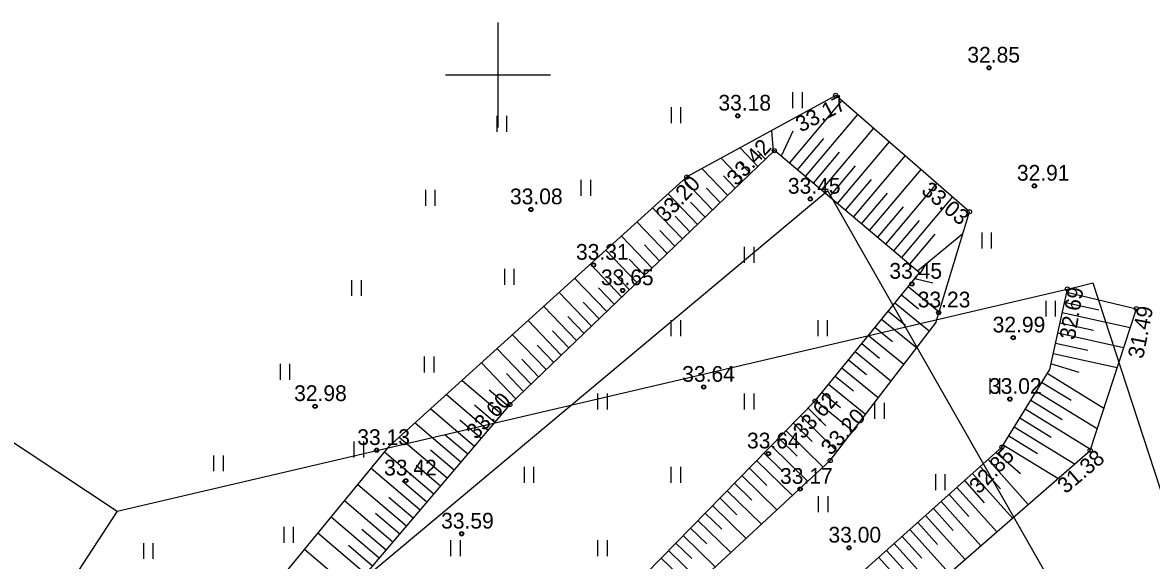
# Model space of a CAD drawing. Extents: x 641898 to 642452, y 6471715 to 6472255.
# Drawn here: x 642027.3 to 642081.1, y 6472226.8 to 6472252.5 of the extents above; entities that cross this region are included whole.
import ezdxf

# ---------------------------------------------------------------- set-up
doc = ezdxf.new("R2010")
doc.units = 0
for name, color, linetype in [('HALJASTUS', 7, 'Continuous'), ('KORGUS-EH2000', 7, 'Continuous'), ('MOOTMPUNKT', 7, 'Continuous'), ('MOOTPIIR', 7, 'Continuous'), ('PIIR', 7, 'Continuous'), ('RELJEEF', 7, 'Continuous'), ('VEEKOGU', 7, 'Continuous'), ('VORK', 7, 'Continuous')]:
    doc.layers.add(name, color=color, linetype=linetype)

msp = doc.modelspace()

# ---------------------------------------------------------------- linework, layer by layer
at = {"layer": 'HALJASTUS'}
for p, q in [((642064.043, 6472249.181), (642064.043, 6472248.42)), ((642064.498, 6472249.181), (642064.498, 6472248.42)), ((642058.249, 6472248.464), (642058.249, 6472247.703)), ((642058.704, 6472248.464), (642058.704, 6472247.703)), ((642049.945, 6472248.046), (642049.945, 6472247.285)), ((642050.4, 6472248.046), (642050.4, 6472247.285)), ((642053.948, 6472244.999), (642053.948, 6472244.238)), ((642054.403, 6472244.999), (642054.403, 6472244.238)), ((642046.54, 6472244.521), (642046.54, 6472243.76)), ((642046.995, 6472244.521), (642046.995, 6472243.76)), ((642073.063, 6472242.49), (642073.063, 6472241.729)), ((642073.518, 6472242.49), (642073.518, 6472241.729)), ((642061.743, 6472241.804), (642061.743, 6472241.043)), ((642062.198, 6472241.804), (642062.198, 6472241.043)), ((642050.304, 6472240.758), (642050.304, 6472239.997)), ((642050.759, 6472240.758), (642050.759, 6472239.997)), ((642043.016, 6472240.22), (642043.016, 6472239.459)), ((642043.471, 6472240.22), (642043.471, 6472239.459)), ((642076.11, 6472239.234), (642076.11, 6472238.473)), ((642076.565, 6472239.234), (642076.565, 6472238.473)), ((642058.243, 6472238.304), (642058.243, 6472237.543)), ((642058.698, 6472238.304), (642058.698, 6472237.543)), ((642065.243, 6472238.304), (642065.243, 6472237.543)), ((642065.698, 6472238.304), (642065.698, 6472237.543)), ((642046.48, 6472236.576), (642046.48, 6472235.815)), ((642046.935, 6472236.576), (642046.935, 6472235.815)), ((642039.611, 6472236.218), (642039.611, 6472235.457)), ((642040.066, 6472236.218), (642040.066, 6472235.457)), ((642073.452, 6472235.531), (642073.452, 6472234.77)), ((642073.907, 6472235.531), (642073.907, 6472234.77)), ((642054.743, 6472234.804), (642054.743, 6472234.043)), ((642055.198, 6472234.804), (642055.198, 6472234.043)), ((642061.743, 6472234.804), (642061.743, 6472234.043)), ((642062.198, 6472234.804), (642062.198, 6472234.043)), ((642067.956, 6472234.366), (642067.956, 6472233.605)), ((642068.411, 6472234.366), (642068.411, 6472233.605)), ((642043.135, 6472232.514), (642043.135, 6472231.753)), ((642043.59, 6472232.514), (642043.59, 6472231.753)), ((642036.445, 6472231.857), (642036.445, 6472231.096)), ((642036.9, 6472231.857), (642036.9, 6472231.096)), ((642051.243, 6472231.304), (642051.243, 6472230.543)), ((642051.698, 6472231.304), (642051.698, 6472230.543)), ((642058.243, 6472231.304), (642058.243, 6472230.543)), ((642058.698, 6472231.304), (642058.698, 6472230.543)), ((642070.853, 6472230.961), (642070.853, 6472230.2)), ((642071.308, 6472230.961), (642071.308, 6472230.2)), ((642065.268, 6472229.915), (642065.268, 6472229.154)), ((642065.723, 6472229.915), (642065.723, 6472229.154)), ((642039.79, 6472228.452), (642039.79, 6472227.691)), ((642040.245, 6472228.452), (642040.245, 6472227.691)), ((642033.099, 6472227.675), (642033.099, 6472226.914)), ((642033.554, 6472227.675), (642033.554, 6472226.914)), ((642047.743, 6472227.804), (642047.743, 6472227.043)), ((642048.198, 6472227.804), (642048.198, 6472227.043)), ((642054.743, 6472227.804), (642054.743, 6472227.043)), ((642055.198, 6472227.804), (642055.198, 6472227.043))]:
    msp.add_line(p, q, dxfattribs=at)
at = {"layer": 'KORGUS-EH2000'}
for centre in [(642073.407, 6472250.341), (642066.098, 6472249.025), (642061.431, 6472248.051), (642063.176, 6472246.392), (642059.006, 6472245.135), (642075.572, 6472244.709), (642064.89, 6472244.088), (642051.57, 6472243.583), (642072.479, 6472243.479), (642054.557, 6472240.937), (642069.73, 6472240.032), (642055.942, 6472239.723), (642077.147, 6472239.79), (642080.432, 6472238.853), (642071.008, 6472238.664), (642074.56, 6472237.469), (642059.803, 6472235.116), (642041.282, 6472234.197), (642050.565, 6472234.28), (642065.121, 6472234.45), (642074.403, 6472234.541), (642044.217, 6472232.101), (642062.892, 6472231.938), (642074.024, 6472232.25), (642078.23, 6472232.093), (642065.837, 6472231.608), (642045.608, 6472230.648), (642064.405, 6472230.25), (642048.27, 6472228.114), (642066.735, 6472227.445)]:
    msp.add_circle(centre, 0.1, dxfattribs=at)
at = {"layer": 'MOOTMPUNKT'}
for centre in [(642073.407, 6472250.341), (642061.431, 6472248.051), (642075.572, 6472244.709), (642064.89, 6472244.088), (642051.57, 6472243.583), (642054.557, 6472240.937), (642069.73, 6472240.032), (642055.942, 6472239.723), (642071.008, 6472238.664), (642074.56, 6472237.469), (642059.803, 6472235.116), (642041.282, 6472234.197), (642074.403, 6472234.541), (642044.217, 6472232.101), (642062.892, 6472231.938), (642045.608, 6472230.648), (642064.405, 6472230.25), (642048.27, 6472228.114), (642066.735, 6472227.445)]:
    msp.add_circle(centre, 0.075, dxfattribs=at)
at = {"layer": 'MOOTPIIR'}
msp.add_lwpolyline([(642014.306, 6472085.384), (642027.67, 6472104.979), (642055.501, 6472084.843), (642081.563, 6472094.262), (642123.938, 6472142.273), (642065.721, 6472244.475), (642008.922, 6472196.948), (642003.347, 6472200.453), (641979.65, 6472162.756), (641979.65, 6472162.756), (641986.045, 6472158.736), (642004.269, 6472142.365), (641987.048, 6472123.488), (641970.482, 6472097.889), (641986.758, 6472084.396)], close=True, dxfattribs=at)
at = {"layer": 'PIIR'}
for p, q in [((642077.68, 6472239.91), (642078.35, 6472240.08)), ((642078.35, 6472240.08), (642090.34, 6472203.36)), ((642031.85, 6472229.19), (642077.68, 6472239.91)), ((642022.295, 6472235.519), (642031.85, 6472229.19)), ((642031.85, 6472229.19), (642000.12, 6472180.55))]:
    msp.add_line(p, q, dxfattribs=at)
at = {"layer": 'RELJEEF'}
for p, q in [((642066.384, 6472248.776), (642063.878, 6472245.801)), ((642067.139, 6472248.12), (642064.642, 6472245.157)), ((642063.037, 6472247.346), (642063.116, 6472246.335)), ((642064.054, 6472247.327), (642063.495, 6472246.123)), ((642067.894, 6472247.464), (642065.407, 6472244.512)), ((642061.545, 6472246.528), (642062.395, 6472245.642)), ((642065.511, 6472246.963), (642064.26, 6472245.479)), ((642068.649, 6472246.808), (642066.172, 6472243.868)), ((642060.637, 6472246.029), (642061.674, 6472244.949)), ((642062.377, 6472246.383), (642062.756, 6472245.988)), ((642066.271, 6472246.313), (642065.025, 6472244.834)), ((642069.404, 6472246.152), (642066.937, 6472243.224)), ((642059.729, 6472245.531), (642060.953, 6472244.257)), ((642061.563, 6472245.787), (642062.035, 6472245.296)), ((642067.03, 6472245.663), (642065.79, 6472244.19)), ((642070.159, 6472245.496), (642067.701, 6472242.579)), ((642058.854, 6472244.998), (642060.232, 6472243.564)), ((642060.748, 6472245.192), (642061.313, 6472244.603)), ((642067.79, 6472245.013), (642066.554, 6472243.546)), ((642059.933, 6472244.596), (642060.592, 6472243.91)), ((642068.55, 6472244.363), (642067.319, 6472242.901)), ((642070.913, 6472244.84), (642068.466, 6472241.935)), ((642058.113, 6472244.326), (642059.51, 6472242.871)), ((642059.177, 6472243.94), (642059.871, 6472243.218)), ((642071.668, 6472244.184), (642069.231, 6472241.291)), ((642057.371, 6472243.655), (642058.789, 6472242.179)), ((642058.446, 6472243.258), (642059.15, 6472242.525)), ((642069.31, 6472243.712), (642068.084, 6472242.257)), ((642056.629, 6472242.984), (642058.068, 6472241.486)), ((642070.07, 6472243.062), (642068.849, 6472241.613)), ((642055.888, 6472242.312), (642057.347, 6472240.793)), ((642057.714, 6472242.576), (642058.428, 6472241.832)), ((642070.83, 6472242.412), (642069.613, 6472240.969)), ((642072.159, 6472242.426), (642069.996, 6472240.646)), ((642055.146, 6472241.641), (642056.625, 6472240.101)), ((642056.983, 6472241.894), (642057.707, 6472241.14)), ((642056.251, 6472241.212), (642056.986, 6472240.447)), ((642054.404, 6472240.969), (642055.904, 6472239.408)), ((642053.663, 6472240.298), (642055.183, 6472238.715)), ((642055.52, 6472240.53), (642056.265, 6472239.754)), ((642070.722, 6472240.069), (642069.865, 6472240.276)), ((642052.921, 6472239.627), (642054.462, 6472238.022)), ((642054.788, 6472239.848), (642055.544, 6472239.062)), ((642070.049, 6472238.837), (642069.234, 6472239.501)), ((642071.024, 6472238.688), (642069.549, 6472239.888)), ((642077.113, 6472239.634), (642080.432, 6472238.853)), ((642052.179, 6472238.955), (642053.74, 6472237.33)), ((642054.057, 6472239.166), (642054.822, 6472238.369)), ((642070.56, 6472237.776), (642068.918, 6472239.113)), ((642078.648, 6472238.783), (642077.005, 6472239.145)), ((642053.326, 6472238.484), (642054.101, 6472237.676)), ((642069.429, 6472238.052), (642068.602, 6472238.725)), ((642080.135, 6472237.943), (642076.897, 6472238.657)), ((642051.438, 6472238.284), (642053.019, 6472236.637)), ((642068.809, 6472237.267), (642067.971, 6472237.95)), ((642069.952, 6472236.982), (642068.286, 6472238.337)), ((642078.385, 6472237.817), (642076.789, 6472238.169)), ((642050.696, 6472237.613), (642052.298, 6472235.944)), ((642052.594, 6472237.802), (642053.38, 6472236.983)), ((642069.343, 6472236.187), (642067.655, 6472237.562)), ((642079.824, 6472236.987), (642076.682, 6472237.681)), ((642049.954, 6472236.941), (642051.577, 6472235.252)), ((642051.863, 6472237.119), (642052.659, 6472236.291)), ((642068.189, 6472236.482), (642067.339, 6472237.174)), ((642078.121, 6472236.851), (642076.574, 6472237.192)), ((642049.212, 6472236.27), (642050.856, 6472234.559)), ((642051.131, 6472236.437), (642051.937, 6472235.598)), ((642067.569, 6472235.697), (642066.708, 6472236.399)), ((642068.735, 6472235.393), (642067.024, 6472236.787)), ((642079.513, 6472236.032), (642076.466, 6472236.704)), ((642050.4, 6472235.755), (642051.216, 6472234.905)), ((642068.127, 6472234.599), (642066.392, 6472236.011)), ((642078.882, 6472234.096), (642076.179, 6472235.757)), ((642077.711, 6472235.807), (642076.358, 6472236.216)), ((642048.289, 6472235.434), (642050.178, 6472233.825)), ((642067.519, 6472233.804), (642065.761, 6472235.236)), ((642066.95, 6472234.912), (642066.076, 6472235.623)), ((642077.32, 6472234.469), (642075.917, 6472235.331)), ((642047.541, 6472234.757), (642049.53, 6472233.064)), ((642049.582, 6472234.989), (642050.502, 6472234.206)), ((642066.33, 6472234.127), (642065.445, 6472234.848)), ((642078.564, 6472233.118), (642075.655, 6472234.905)), ((642048.884, 6472234.27), (642049.854, 6472233.445)), ((642066.91, 6472233.01), (642065.129, 6472234.46)), ((642076.899, 6472233.554), (642075.393, 6472234.479)), ((642046.793, 6472234.08), (642048.881, 6472232.302)), ((642066.17, 6472232.043), (642064.431, 6472233.745)), ((642065.628, 6472233.272), (642064.78, 6472234.102)), ((642076.371, 6472232.704), (642074.87, 6472233.627)), ((642078.245, 6472232.14), (642075.132, 6472234.053)), ((642046.046, 6472233.403), (642048.233, 6472231.541)), ((642048.186, 6472233.551), (642049.206, 6472232.683)), ((642065.502, 6472231.297), (642063.731, 6472233.03)), ((642064.972, 6472232.515), (642064.081, 6472233.387)), ((642077.478, 6472231.437), (642074.608, 6472233.201)), ((642045.298, 6472232.726), (642047.585, 6472230.779)), ((642047.488, 6472232.832), (642048.557, 6472231.922)), ((642064.258, 6472231.815), (642063.382, 6472232.673)), ((642075.715, 6472231.934), (642074.346, 6472232.775)), ((642044.586, 6472232.019), (642046.937, 6472230.018)), ((642046.79, 6472232.112), (642047.909, 6472231.16)), ((642063.541, 6472231.118), (642062.682, 6472231.958)), ((642064.767, 6472230.617), (642063.032, 6472232.315)), ((642074.904, 6472230.969), (642073.738, 6472231.994)), ((642076.689, 6472230.748), (642074.085, 6472232.349)), ((642064.032, 6472229.937), (642062.332, 6472231.601)), ((642075.281, 6472229.52), (642073.365, 6472231.66)), ((642043.951, 6472231.246), (642046.289, 6472229.257)), ((642046.093, 6472231.393), (642047.261, 6472230.399)), ((642063.297, 6472229.257), (642061.633, 6472230.886)), ((642062.824, 6472230.42), (642061.983, 6472231.243)), ((642074.528, 6472228.862), (642072.62, 6472230.993)), ((642073.948, 6472230.259), (642072.993, 6472231.327)), ((642043.317, 6472230.473), (642045.64, 6472228.495)), ((642045.441, 6472230.635), (642046.613, 6472229.637)), ((642062.107, 6472229.723), (642061.283, 6472230.529)), ((642073.199, 6472229.597), (642072.247, 6472230.66)), ((642044.799, 6472229.868), (642045.964, 6472228.876)), ((642061.39, 6472229.025), (642060.584, 6472229.814)), ((642062.563, 6472228.577), (642060.933, 6472230.171)), ((642072.45, 6472228.934), (642071.502, 6472229.993)), ((642073.774, 6472228.205), (642071.875, 6472230.327)), ((642042.682, 6472229.7), (642044.992, 6472227.734)), ((642061.828, 6472227.896), (642060.234, 6472229.457)), ((642071.7, 6472228.272), (642070.757, 6472229.326)), ((642073.02, 6472227.547), (642071.13, 6472229.66)), ((642042.047, 6472228.927), (642044.344, 6472226.972)), ((642044.158, 6472229.101), (642045.316, 6472228.114)), ((642061.093, 6472227.216), (642059.534, 6472228.742)), ((642060.672, 6472228.328), (642059.884, 6472229.099)), ((642072.267, 6472226.89), (642070.385, 6472228.993)), ((642043.516, 6472228.333), (642044.668, 6472227.353)), ((642059.955, 6472227.63), (642059.185, 6472228.385)), ((642071.513, 6472226.232), (642069.639, 6472228.326)), ((642070.951, 6472227.61), (642070.012, 6472228.659)), ((642041.413, 6472228.154), (642043.696, 6472226.211)), ((642059.238, 6472226.933), (642058.485, 6472227.67)), ((642060.359, 6472226.536), (642058.835, 6472228.027)), ((642070.76, 6472225.574), (642068.894, 6472227.659)), ((642070.202, 6472226.948), (642069.267, 6472227.992)), ((642040.778, 6472227.381), (642043.047, 6472225.449)), ((642042.875, 6472227.566), (642044.02, 6472226.591)), ((642059.624, 6472225.856), (642058.135, 6472227.313)), ((642069.452, 6472226.286), (642068.522, 6472227.325)), ((642058.521, 6472226.236), (642057.786, 6472226.955)), ((642070.017, 6472224.905), (642068.149, 6472226.992))]:
    msp.add_line(p, q, dxfattribs=at)
for points in [[(642021.238, 6472203.161), (642020.615, 6472199.823), (642026.15, 6472194.605), (642027.937, 6472194.569), (642041.15, 6472208.366), (642054.15, 6472220.788), (642065.837, 6472231.608), (642070.87, 6472238.181), (642072.479, 6472243.479), (642066.098, 6472249.025), (642059.006, 6472245.135), (642044.784, 6472232.261), (642029.401, 6472213.522), (642021.238, 6472203.161)], [(642027.203, 6472195.68), (642039.818, 6472209.09), (642052.598, 6472221.655), (642065.121, 6472234.45), (642070.097, 6472240.561), (642063.176, 6472246.392), (642050.565, 6472234.28), (642039.282, 6472221.026), (642024.335, 6472202.568), (642023.321, 6472200.131), (642027.203, 6472195.68)], [(642029.934, 6472187.506), (642033.4, 6472192.669), (642045.53, 6472204.858), (642058.758, 6472218.587), (642074.024, 6472232.25), (642076.301, 6472235.956), (642077.147, 6472239.79)]]:
    msp.add_lwpolyline(points, dxfattribs=at)
at = {"layer": 'VEEKOGU'}
msp.add_lwpolyline([(642033.614, 6472188.229), (642040.787, 6472195.783), (642053.843, 6472208.83), (642070.199, 6472225.085), (642078.23, 6472232.093), (642080.432, 6472238.853)], dxfattribs=at)
at = {"layer": 'VORK'}
for p, q in [((642050, 6472252.5), (642050, 6472247.5)), ((642047.5, 6472250), (642052.5, 6472250))]:
    msp.add_line(p, q, dxfattribs=at)

# ---------------------------------------------------------------- texts
at = {"layer": 'KORGUS-EH2000'}
for s, p in [('32.85', (642072.374, 6472250.591)), ('33.18', (642060.508, 6472248.301)), ('32.91', (642074.735, 6472244.959)), ('33.45', (642063.819, 6472244.338)), ('33.08', (642050.572, 6472243.833)), ('33.31', (642053.72, 6472241.187)), ('33.65', (642054.909, 6472239.973)), ('33.45', (642068.659, 6472240.282)), ('33.23', (642070.01, 6472238.914)), ('32.99', (642073.58, 6472237.719)), ('33.64', (642058.782, 6472235.366)), ('32.98', (642040.284, 6472234.447)), ('33.02', (642073.405, 6472234.791)), ('33.13', (642043.294, 6472232.351)), ('33.64', (642061.871, 6472232.188)), ('33.42', (642044.573, 6472230.898)), ('33.17', (642063.447, 6472230.5)), ('33.59', (642047.29, 6472228.364)), ('33.00', (642065.753, 6472227.695))]:
    msp.add_text(s, height=0.75, dxfattribs=at).set_placement(p)
for s, rotation, p in [('33.17', 27.4201, (642064.439, 6472247.249)), ('33.42', 47.2741, (642061.377, 6472244.668)), ('33.20', 47.2741, (642057.992, 6472242.926)), ('33.03', 319.7356, (642070.133, 6472244.409)), ('32.69', 80.2564, (642077.497, 6472237.334)), ('31.49', 78.7812, (642080.751, 6472236.432)), ('33.60', 47.2741, (642048.966, 6472232.573)), ('33.62', 47.2741, (642064.537, 6472232.59)), ('33.20', 47.2741, (642065.869, 6472231.816)), ('32.85', 46.023, (642072.924, 6472229.973)), ('31.38', 40.1882, (642077.062, 6472229.992))]:
    msp.add_text(s, height=0.75, rotation=rotation, dxfattribs=at).set_placement(p)

doc.saveas('drawing.dxf')
